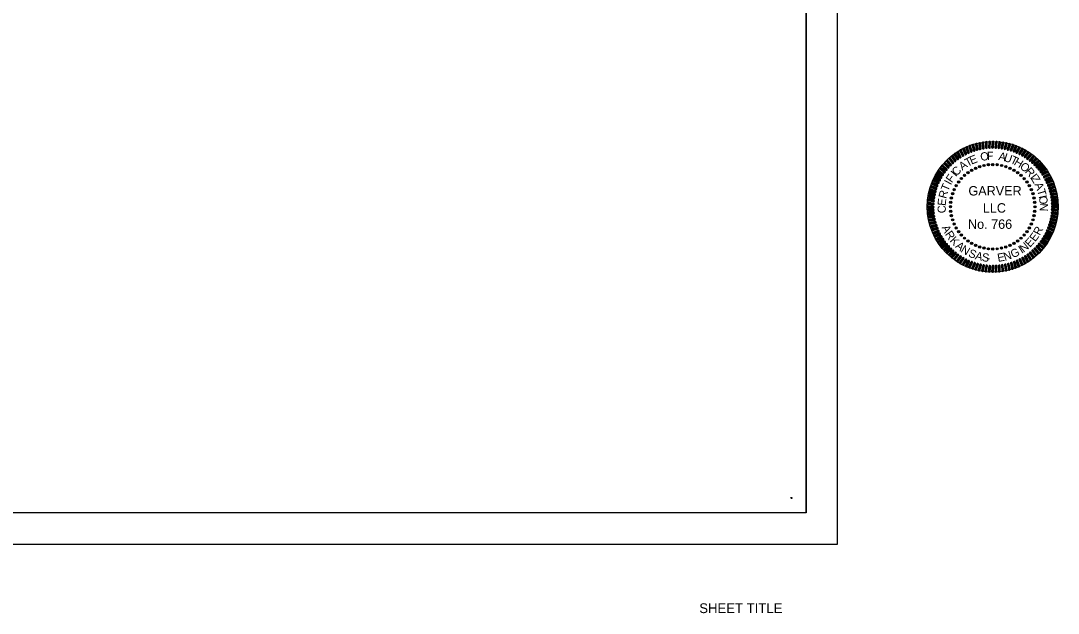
# Model space of a CAD drawing. Extents: x 0 to 19, y -0.6 to 11.5.
# Drawn here: x 9.51 to 19.02, y -0.63 to 4.8 of the extents above; entities that cross this region are included whole.
import ezdxf

# ---------------------------------------------------------------- set-up
doc = ezdxf.new("R2010")
doc.units = 0
for name, color, linetype in [('G-ANNO-STMP', 7, 'Continuous'), ('G-ANNO-TEXT', 7, 'Continuous'), ('G-Border-Paper', 7, 'Continuous'), ('G-Border-Sheet', 7, 'Continuous'), ('G-No Plot-Anchor', 7, 'Continuous'), ('G-No Plot-Border-1', 7, 'Continuous'), ('G-No Plot-Border-2', 7, 'Continuous'), ('G-No Plot-Stamp-1', 7, 'Continuous')]:
    doc.layers.add(name, color=color, linetype=linetype)

# ---------------------------------------------------------------- blocks, each defined once
blk = doc.blocks.new('SEALDO')
at = {"layer": 'G-ANNO-TEXT'}
for radius in [0.0396, 0.0305, 0.0213, 0.0122, 0.00305]:
    blk.add_circle((1.403, -0.456), radius, dxfattribs=at)
blk = doc.blocks.new('SEALRI')
at = {"layer": 'G-ANNO-TEXT'}
for p, q in [((-0.023, 2.258), (-0.038, 2.081)), ((-0.008, 2.281), (-0.028, 2.056)), ((0.004, 2.286), (-0.016, 2.049)), ((0.016, 2.285), (-0.004, 2.048)), ((0.028, 2.278), (0.008, 2.052)), ((0.023, 2.076), (0.038, 2.253))]:
    blk.add_line(p, q, dxfattribs=at)
for centre, start, end in [((0.008, 2.256), 355, 175), ((-0.008, 2.078), 175, 355)]:
    blk.add_arc(centre, 0.0305, start, end, dxfattribs=at)

msp = doc.modelspace()

# ---------------------------------------------------------------- linework, layer by layer
at = {"layer": 'G-Border-Paper'}
msp.add_lwpolyline([(17, 11), (0, 11), (0, 0), (17, 0)], close=True, dxfattribs=at)
at = {"layer": 'G-Border-Sheet'}
for q in [(16.7116, 10.7116), (0.758, 0.2884)]:
    msp.add_line((16.7116, 0.2884), q, dxfattribs=at)
at = {"layer": 'G-No Plot-Anchor'}
msp.add_circle((16.5766, 0.4234), 0.005, dxfattribs=at)
at = {"layer": 'G-No Plot-Border-1'}
msp.add_lwpolyline([(0.758, 0.2884), (0.758, 10.7116), (13.7281, 10.7116), (13.7281, 10.2161), (15.4366, 10.2161), (15.4366, 8.7411), (16.7116, 8.7411), (16.7116, 0.2884)], close=True, dxfattribs=at)
at = {"layer": 'G-No Plot-Border-2'}
msp.add_lwpolyline([(0.758, 0.2884), (0.758, 10.7116), (12.3781, 10.7116), (12.3781, 9.2366), (13.7281, 9.2366), (13.7281, 10.2161), (14.7206, 10.2161), (16.7116, 10.2161), (16.7116, 0.2884)], close=True, dxfattribs=at)
at = {"layer": 'G-No Plot-Stamp-1'}
msp.add_circle((18.4222, 3.0925), 0.6, dxfattribs=at)

# ---------------------------------------------------------------- block references
at = {"layer": 'G-ANNO-STMP'}
for name, xscale, yscale, rotation in [('SEALRI', 0.2624620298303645, 0.2624620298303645, 30.00000000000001), ('SEALRI', 0.2624620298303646, 0.26246202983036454, 26.99999999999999), ('SEALRI', 0.26246202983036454, 0.26246202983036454, 23.99999999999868), ('SEALRI', 0.26246202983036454, 0.26246202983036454, 20.999999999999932), ('SEALRI', 0.2624620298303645, 0.26246202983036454, 18), ('SEALRI', 0.2624620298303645, 0.2624620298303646, 15.000000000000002), ('SEALRI', 0.2624620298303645, 0.2624620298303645, 12.000000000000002), ('SEALRI', 0.2624620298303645, 0.2624620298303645, 9), ('SEALRI', 0.2624620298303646, 0.26246202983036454, 6), ('SEALRI', 0.2624620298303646, 0.2624620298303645, 3.0000000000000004), ('SEALRI', 0.26246202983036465, 0.2624620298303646, -2.9999999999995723), ('SEALRI', 0.2624620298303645, 0.2624620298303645, -5.9999999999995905), ('SEALRI', 0.2624620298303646, 0.26246202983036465, -8.999999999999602), ('SEALRI', 0.2624620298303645, 0.26246202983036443, -11.999999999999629), ('SEALRI', 0.2624620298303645, 0.2624620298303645, -14.999999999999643), ('SEALRI', 0.26246202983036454, 0.2624620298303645, -17.99999999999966), ('SEALRI', 0.2624620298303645, 0.26246202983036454, -20.999999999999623), ('SEALRI', 0.2624620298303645, 0.26246202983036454, -23.999999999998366), ('SEALRI', 0.26246202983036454, 0.26246202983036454, -26.999999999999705), ('SEALRI', 0.26246202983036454, 0.2624620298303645, -29.99999999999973), ('SEALRI', 0.26246202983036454, 0.2624620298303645, 44.999999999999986), ('SEALRI', 0.26246202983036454, 0.2624620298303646, 41.999999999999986), ('SEALRI', 0.26246202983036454, 0.26246202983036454, 38.999999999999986), ('SEALRI', 0.2624620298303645, 0.2624620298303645, 36), ('SEALRI', 0.2624620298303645, 0.26246202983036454, 33), ('SEALRI', 0.26246202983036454, 0.2624620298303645, -32.999999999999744), ('SEALRI', 0.2624620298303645, 0.2624620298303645, -35.999999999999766), ('SEALRI', 0.26246202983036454, 0.2624620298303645, -38.999999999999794), ('SEALRI', 0.26246202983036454, 0.2624620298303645, -41.99999999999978), ('SEALRI', 0.26246202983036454, 0.2624620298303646, -44.999999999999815), ('SEALRI', 0.26246202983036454, 0.2624620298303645, 56.99999999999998), ('SEALRI', 0.2624620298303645, 0.2624620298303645, 54), ('SEALRI', 0.26246202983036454, 0.26246202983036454, 50.99999999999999), ('SEALRI', 0.2624620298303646, 0.26246202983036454, 47.99999999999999), ('SEALDO', 0.26246202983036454, 0.26246202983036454, 138), ('SEALDO', 0.2624620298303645, 0.26246202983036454, 131.99999999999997), ('SEALDO', 0.2624620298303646, 0.26246202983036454, 125.99999999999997), ('SEALDO', 0.2624620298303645, 0.26246202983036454, 119.99999999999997), ('SEALDO', 0.2624620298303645, 0.26246202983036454, 113.99999999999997), ('SEALDO', 0.26246202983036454, 0.2624620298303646, 107.99999999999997), ('SEALDO', 0.26246202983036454, 0.26246202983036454, 101.99999999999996), ('SEALDO', 0.2624620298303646, 0.2624620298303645, 95.99999999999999), ('SEALDO', 0.26246202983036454, 0.26246202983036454, 90), ('SEALDO', 0.2624620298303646, 0.26246202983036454, 83.99999999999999), ('SEALDO', 0.2624620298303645, 0.26246202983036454, 77.99999999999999), ('SEALRI', 0.26246202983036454, 0.2624620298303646, -47.99999999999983), ('SEALRI', 0.2624620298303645, 0.26246202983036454, -50.999999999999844), ('SEALRI', 0.2624620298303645, 0.26246202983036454, -53.99999999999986), ('SEALRI', 0.2624620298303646, 0.26246202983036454, -56.999999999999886), ('SEALRI', 0.26246202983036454, 0.2624620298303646, 65.99999999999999), ('SEALRI', 0.26246202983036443, 0.2624620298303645, 63), ('SEALRI', 0.2624620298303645, 0.2624620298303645, 59.999999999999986), ('SEALDO', 0.2624620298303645, 0.26246202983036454, 162.00000000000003), ('SEALDO', 0.26246202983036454, 0.2624620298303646, 156.00000000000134), ('SEALDO', 0.26246202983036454, 0.2624620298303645, 150), ('SEALDO', 0.2624620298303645, 0.26246202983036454, 144), ('SEALDO', 0.2624620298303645, 0.26246202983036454, 72), ('SEALDO', 0.26246202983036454, 0.2624620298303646, 66.00000000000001), ('SEALDO', 0.26246202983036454, 0.2624620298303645, 60.00000000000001), ('SEALDO', 0.2624620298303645, 0.2624620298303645, 54), ('SEALRI', 0.2624620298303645, 0.26246202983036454, -59.99999999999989), ('SEALRI', 0.2624620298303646, 0.26246202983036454, -62.99999999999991), ('SEALRI', 0.26246202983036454, 0.2624620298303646, -65.99999999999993), ('SEALRI', 0.2624620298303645, 0.26246202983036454, 75.00000000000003), ('SEALRI', 0.2624620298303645, 0.26246202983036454, 72), ('SEALRI', 0.26246202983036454, 0.2624620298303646, 68.99999999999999), ('SEALDO', 0.2624620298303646, 0.2624620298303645, 174.00000000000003), ('SEALDO', 0.26246202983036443, 0.2624620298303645, 168.00000000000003), ('SEALDO', 0.26246202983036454, 0.2624620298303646, 48.00000000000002), ('SEALDO', 0.2624620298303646, 0.26246202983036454, 42.000000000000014), ('SEALRI', 0.26246202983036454, 0.26246202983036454, -68.99999999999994), ('SEALRI', 0.26246202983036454, 0.26246202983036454, -71.99999999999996), ('SEALRI', 0.26246202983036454, 0.2624620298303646, -74.99999999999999), ('SEALRI', 0.2624620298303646, 0.26246202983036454, 84.00000000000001), ('SEALRI', 0.2624620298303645, 0.2624620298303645, 81), ('SEALRI', 0.2624620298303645, 0.2624620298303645, 78.00000000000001), ('SEALDO', 0.2624620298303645, 0.26246202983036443, -167.99999999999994), ('SEALDO', 0.26246202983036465, 0.26246202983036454, -173.99999999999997), ('SEALDO', 0.26246202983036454, 0.26246202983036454, -179.99999999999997), ('SEALDO', 0.2624620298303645, 0.2624620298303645, 36), ('SEALDO', 0.26246202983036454, 0.2624620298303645, 29.999999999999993), ('SEALDO', 0.26246202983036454, 0.26246202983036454, 23.99999999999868), ('SEALRI', 0.2624620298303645, 0.2624620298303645, -78), ('SEALRI', 0.2624620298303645, 0.2624620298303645, -81.00000000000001), ('SEALRI', 0.2624620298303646, 0.2624620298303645, -84.00000000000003), ('SEALRI', 0.26246202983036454, 0.26246202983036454, 90.00000000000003), ('SEALRI', 0.26246202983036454, 0.26246202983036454, 87.00000000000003), ('SEALRI', 0.2624620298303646, 0.2624620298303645, 93), ('SEALRI', 0.2624620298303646, 0.26246202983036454, 96.00000000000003), ('SEALDO', 0.2624620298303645, 0.26246202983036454, -161.99999999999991), ('SEALDO', 0.2624620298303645, 0.26246202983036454, -156.00000000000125), ('SEALDO', 0.2624620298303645, 0.2624620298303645, 12.000000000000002), ('SEALDO', 0.2624620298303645, 0.26246202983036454, 18), ('SEALRI', 0.26246202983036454, 0.2624620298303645, -96.0000000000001), ('SEALRI', 0.26246202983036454, 0.26246202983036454, -87.00000000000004), ('SEALRI', 0.2624620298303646, 0.26246202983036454, -93.00000000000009), ('SEALRI', 0.26246202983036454, 0.26246202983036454, -90.00000000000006), ('SEALRI', 0.26246202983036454, 0.26246202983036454, 99.00000000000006), ('SEALRI', 0.2624620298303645, 0.2624620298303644, 102.00000000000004), ('SEALRI', 0.26246202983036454, 0.2624620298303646, 105.00000000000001), ('SEALDO', 0.26246202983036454, 0.26246202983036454, -149.99999999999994), ('SEALDO', 0.2624620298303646, 0.26246202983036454, -143.99999999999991), ('SEALDO', 0.26246202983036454, 0.2624620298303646, -137.9999999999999), ('SEALDO', 0.2624620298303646, 0.26246202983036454, 6), ('SEALRI', 0.26246202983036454, 0.2624620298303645, -105.00000000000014), ('SEALRI', 0.2624620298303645, 0.2624620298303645, -102.00000000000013), ('SEALRI', 0.26246202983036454, 0.2624620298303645, -99.00000000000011), ('SEALRI', 0.26246202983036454, 0.26246202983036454, 108.00000000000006), ('SEALRI', 0.2624620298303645, 0.2624620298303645, 111.00000000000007), ('SEALRI', 0.26246202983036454, 0.26246202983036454, 114.00000000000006), ('SEALRI', 0.26246202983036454, 0.26246202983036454, 117.00000000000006), ('SEALDO', 0.26246202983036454, 0.26246202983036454, -131.99999999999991), ('SEALDO', 0.26246202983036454, 0.2624620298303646, -125.9999999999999), ('SEALDO', 0.2624620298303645, 0.26246202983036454, -18.000000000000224), ('SEALDO', 0.2624620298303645, 0.26246202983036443, -12.000000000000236), ('SEALDO', 0.26246202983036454, 0.2624620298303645, -6.000000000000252), ('SEALRI', 0.26246202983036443, 0.2624620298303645, -117.00000000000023), ('SEALRI', 0.26246202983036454, 0.2624620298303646, -114.0000000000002), ('SEALRI', 0.26246202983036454, 0.26246202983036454, -111.00000000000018), ('SEALRI', 0.26246202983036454, 0.2624620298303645, -108.00000000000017), ('SEALRI', 0.2624620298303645, 0.2624620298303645, 120.00000000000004), ('SEALRI', 0.2624620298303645, 0.2624620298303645, 123.00000000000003), ('SEALRI', 0.26246202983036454, 0.26246202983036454, 126.00000000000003), ('SEALRI', 0.26246202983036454, 0.26246202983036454, 129.00000000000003), ('SEALDO', 0.2624620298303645, 0.26246202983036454, -119.99999999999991), ('SEALDO', 0.26246202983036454, 0.26246202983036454, -113.99999999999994), ('SEALDO', 0.26246202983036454, 0.26246202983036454, -107.99999999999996), ('SEALDO', 0.2624620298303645, 0.26246202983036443, -101.99999999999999), ('SEALDO', 0.2624620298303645, 0.2624620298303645, -42.00000000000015), ('SEALDO', 0.2624620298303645, 0.2624620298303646, -36.00000000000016), ('SEALDO', 0.2624620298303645, 0.26246202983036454, -30.00000000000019), ('SEALDO', 0.26246202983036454, 0.2624620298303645, -23.999999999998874), ('SEALRI', 0.2624620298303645, 0.26246202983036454, -129.00000000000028), ('SEALRI', 0.26246202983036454, 0.2624620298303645, -126.00000000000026), ('SEALRI', 0.2624620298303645, 0.26246202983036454, -123.00000000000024), ('SEALRI', 0.26246202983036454, 0.2624620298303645, -120.00000000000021), ('SEALRI', 0.26246202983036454, 0.2624620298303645, 132), ('SEALRI', 0.2624620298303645, 0.26246202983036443, 135), ('SEALRI', 0.26246202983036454, 0.26246202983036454, 138), ('SEALRI', 0.2624620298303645, 0.26246202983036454, 140.99999999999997), ('SEALRI', 0.2624620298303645, 0.26246202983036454, 144), ('SEALDO', 0.2624620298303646, 0.26246202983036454, -96), ('SEALDO', 0.26246202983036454, 0.26246202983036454, -90.00000000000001), ('SEALDO', 0.2624620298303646, 0.2624620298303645, -84.00000000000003), ('SEALDO', 0.26246202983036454, 0.26246202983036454, -78.00000000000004), ('SEALDO', 0.26246202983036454, 0.2624620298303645, -72.00000000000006), ('SEALDO', 0.2624620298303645, 0.26246202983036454, -66.00000000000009), ('SEALDO', 0.26246202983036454, 0.26246202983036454, -60.0000000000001), ('SEALDO', 0.26246202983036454, 0.26246202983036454, -54.000000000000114), ('SEALDO', 0.26246202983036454, 0.26246202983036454, -48.00000000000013), ('SEALRI', 0.2624620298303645, 0.26246202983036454, -144.00000000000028), ('SEALRI', 0.26246202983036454, 0.2624620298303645, -141.0000000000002), ('SEALRI', 0.26246202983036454, 0.2624620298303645, -138.00000000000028), ('SEALRI', 0.2624620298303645, 0.2624620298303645, -135.00000000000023), ('SEALRI', 0.2624620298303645, 0.26246202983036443, -132.00000000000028), ('SEALRI', 0.2624620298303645, 0.26246202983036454, 146.99999999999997), ('SEALRI', 0.2624620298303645, 0.26246202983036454, 149.99999999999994), ('SEALRI', 0.2624620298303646, 0.26246202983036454, 152.99999999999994), ('SEALRI', 0.2624620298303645, 0.2624620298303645, 156.00000000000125), ('SEALRI', 0.2624620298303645, 0.26246202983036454, 159), ('SEALRI', 0.2624620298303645, 0.2624620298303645, 161.99999999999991), ('SEALRI', 0.2624620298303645, 0.26246202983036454, 164.99999999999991), ('SEALRI', 0.2624620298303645, 0.26246202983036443, 167.99999999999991), ('SEALRI', 0.2624620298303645, 0.2624620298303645, -168.0000000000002), ('SEALRI', 0.2624620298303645, 0.2624620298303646, -165.0000000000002), ('SEALRI', 0.2624620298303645, 0.26246202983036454, -162.00000000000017), ('SEALRI', 0.26246202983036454, 0.26246202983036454, -159.00000000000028), ('SEALRI', 0.2624620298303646, 0.2624620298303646, -156.00000000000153), ('SEALRI', 0.2624620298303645, 0.2624620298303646, -153.00000000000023), ('SEALRI', 0.2624620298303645, 0.26246202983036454, -150.00000000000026), ('SEALRI', 0.26246202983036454, 0.2624620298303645, -147.00000000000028), ('SEALRI', 0.26246202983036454, 0.2624620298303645, 170.9999999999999), ('SEALRI', 0.26246202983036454, 0.2624620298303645, 173.9999999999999), ('SEALRI', 0.2624620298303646, 0.2624620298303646, 176.9999999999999), ('SEALRI', 0.26246202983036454, 0.26246202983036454, 179.99999999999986), ('SEALRI', 0.2624620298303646, 0.26246202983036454, -177.00000000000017), ('SEALRI', 0.2624620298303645, 0.2624620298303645, -174.00000000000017), ('SEALRI', 0.26246202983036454, 0.2624620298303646, -171.00000000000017)]:
    msp.add_blockref(name, (18.4223, 3.0925), dxfattribs=dict(at, xscale=xscale, yscale=yscale, rotation=rotation))
at = {"layer": 'G-ANNO-STMP', "xscale": 0.26246202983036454, "yscale": 0.26246202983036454}
for name in ['SEALRI', 'SEALDO']:
    msp.add_blockref(name, (18.4223, 3.0925), dxfattribs=at)

# ---------------------------------------------------------------- texts
at = {"layer": 'G-ANNO-STMP'}
for s, rotation, p in [('T', 28.2771, (18.1905, 3.4573)), ('E', 21.61044, (18.2267, 3.4785)), ('O', 8.2771, (18.3136, 3.5123)), ('F', 1.61044, (18.3705, 3.522)), ('A', 348.2771, (18.4707, 3.5227)), ('U', 341.27715, (18.5176, 3.5152)), ('T', 334.94377, (18.5765, 3.4962)), ('H', 328.2771, (18.6103, 3.4828)), ('I', 49.74076, (18.0858, 3.3622)), ('C', 44.38813, (18.0896, 3.3699)), ('A', 34.94377, (18.1428, 3.4228)), ('O', 319.7874, (18.6645, 3.452)), ('R', 311.99331, (18.7137, 3.4128)), ('I', 61.61044, (18.0378, 3.2871)), ('F', 54.94377, (18.0468, 3.3073)), ('I', 307.00814, (18.7595, 3.3613)), ('Z', 301.61044, (18.7683, 3.3523)), ('R', 74.94377, (17.9951, 3.1629)), ('T', 67.43139, (18.0126, 3.2289)), ('A', 292.97516, (18.8037, 3.2978)), ('T', 286.3085, (18.8272, 3.2435)), ('E', 83.89849, (17.9897, 3.0987)), ('I', 281.61044, (18.8422, 3.1908)), ('O', 276.48226, (18.8451, 3.1881)), ('C', 91.88416, (17.993, 3.0347)), ('N', 268.2771, (18.8545, 3.1248)), ('A', 296.57465, (17.9514, 2.9025)), ('R', 304.61826, (17.981, 2.8408)), ('E', 54.73091, (18.8126, 2.7672)), ('R', 63.09594, (18.8543, 2.8247)), ('K', 313.3805, (18.0231, 2.778)), ('A', 321.25836, (18.0738, 2.7232)), ('N', 38.98211, (18.705, 2.6701)), ('E', 46.68075, (18.7629, 2.7159)), ('N', 329.10994, (18.1231, 2.6817)), ('S', 337.62936, (18.1923, 2.6396)), ('A', 345.40726, (18.2555, 2.613)), ('S', 352.80457, (18.3191, 2.5952)), ('E', 10.06947, (18.4713, 2.5871)), ('N', 17.86862, (18.5341, 2.5965)), ('G', 26.41319, (18.608, 2.6194)), ('I', 32.97899, (18.6876, 2.6612)), ('-', 0.83848, (18.3644, 2.5854))]:
    msp.add_text(s, height=0.075, rotation=rotation, dxfattribs=at).set_placement(p)
for s, p in [('GARVER', (18.1993, 3.1961)), ('LLC', (18.3314, 3.039)), ('No. 766', (18.1956, 2.8903))]:
    msp.add_text(s, height=0.0864, dxfattribs=at).set_placement(p)
at = {"layer": 'G-ANNO-TEXT'}
msp.add_text('SHEET TITLE', height=0.09, dxfattribs=at).set_placement((15.7319, -0.6318))

doc.saveas('drawing.dxf')
